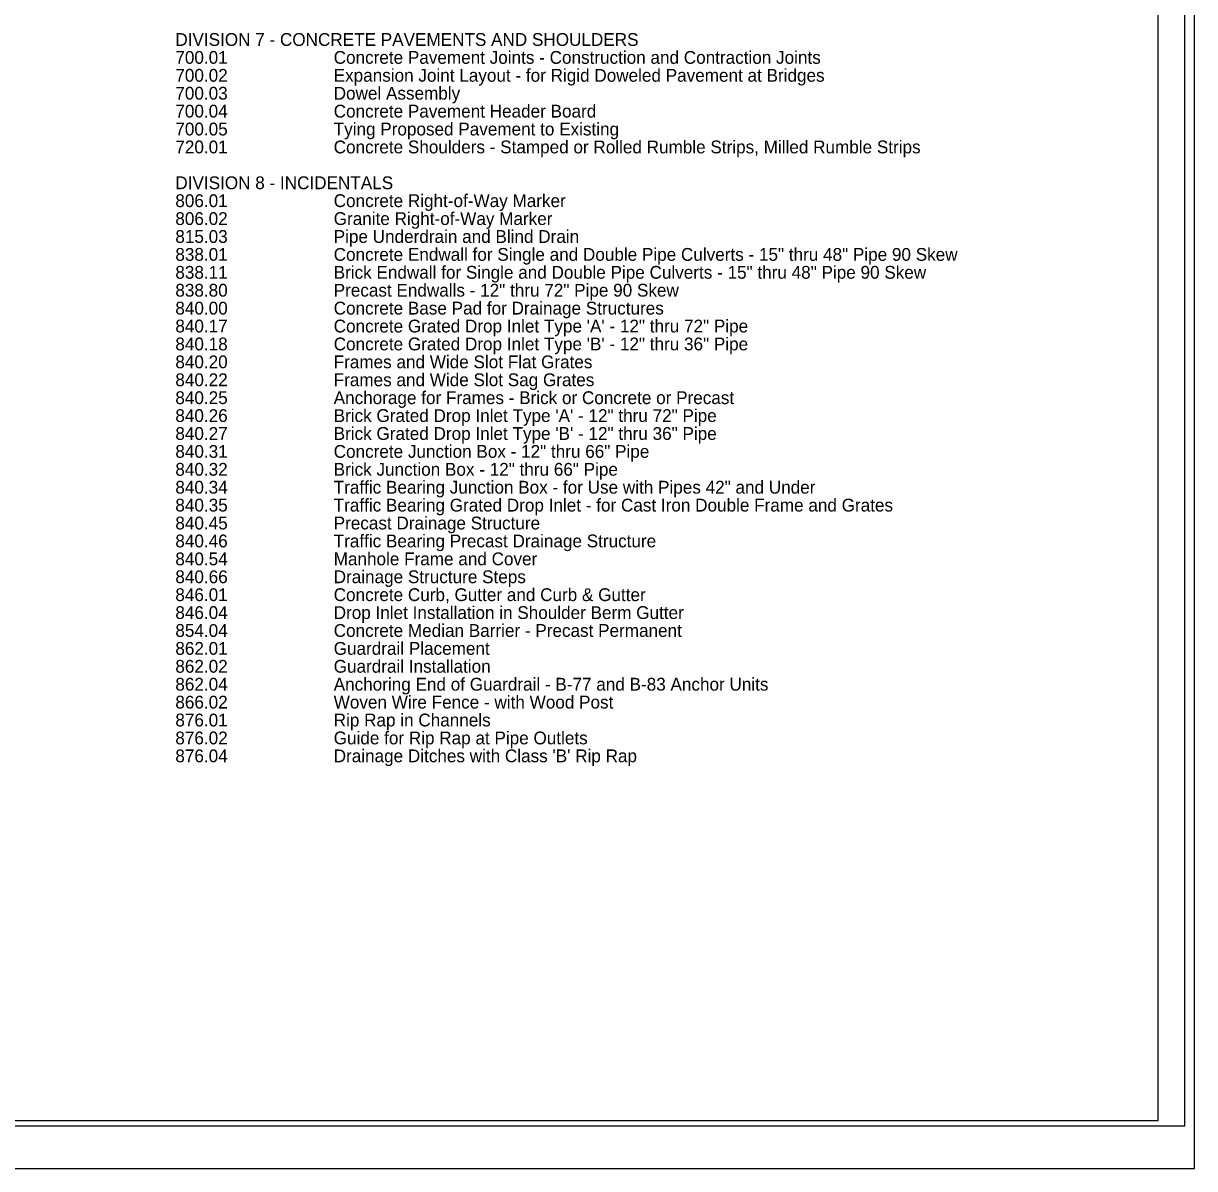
# Model space of a CAD drawing. Extents: x 2241278 to 2254132, y 649924 to 670434.
# Drawn here: x 2250231 to 2252976, y 649924 to 652610 of the extents above; entities that cross this region are included whole.
import ezdxf

# ---------------------------------------------------------------- set-up
doc = ezdxf.new("R2010")
doc.units = 0
for name, color, linetype in [('Sheet Cutting Line CELL', 7, 'Continuous'), ('Sheet Data Text CELL', 7, 'Continuous'), ('Sheet Plan CELL', 7, 'Continuous'), ('Sheet Plot Border Inside CELL', 7, 'Continuous'), ('Sheet Plot Border Outside CELL', 7, 'Continuous')]:
    doc.layers.add(name, color=color, linetype=linetype)

msp = doc.modelspace()

# ---------------------------------------------------------------- linework, layer by layer
at = {"layer": 'Sheet Cutting Line CELL'}
msp.add_line((2244558.8, 649924.2), (2252976.3, 649924.2), dxfattribs=at)
at = {"layer": 'Sheet Plan CELL'}
msp.add_lwpolyline([(2252891.3, 655286.7), (2245391.3, 655286.7), (2245391.3, 650036.7), (2252891.3, 650036.7)], close=True, dxfattribs=at)
at = {"layer": 'Sheet Plot Border Inside CELL'}
msp.add_lwpolyline([(2244623.8, 650024.2), (2252953.8, 650024.2), (2252953.8, 655299.2), (2244623.8, 655299.2)], close=True, dxfattribs=at)
at = {"layer": 'Sheet Plot Border Outside CELL'}
msp.add_lwpolyline([(2244558.8, 649924.2), (2252976.3, 649924.2), (2252976.3, 655399.2), (2244558.8, 655399.2)], close=True, dxfattribs=at)

# ---------------------------------------------------------------- texts
at = {"layer": 'Sheet Data Text CELL'}
for s, p in [('DIVISION 7 - CONCRETE PAVEMENTS AND SHOULDERS', (2250587.3, 652557.1)), ('700.01', (2250587.3, 652515.1)), (' Concrete Pavement Joints - Construction and Contraction Joints ', (2250947.3, 652515.1)), (' Expansion Joint Layout - for Rigid Doweled Pavement at Bridges', (2250947.3, 652473.1)), ('700.02', (2250587.3, 652473.1)), ('700.03', (2250587.3, 652431.1)), (' Dowel Assembly', (2250947.3, 652431.1)), ('700.04', (2250587.3, 652389.1)), (' Concrete Pavement Header Board', (2250947.3, 652389.1)), ('700.05', (2250587.3, 652347.1)), (' Tying Proposed Pavement to Existing', (2250947.3, 652347.1)), ('720.01', (2250587.3, 652305.1)), (' Concrete Shoulders - Stamped or Rolled Rumble Strips, Milled Rumble Strips', (2250947.3, 652305.1)), ('DIVISION 8 - INCIDENTALS', (2250587.3, 652221.1)), ('806.01', (2250587.3, 652179.1)), (' Concrete Right-of-Way Marker', (2250947.3, 652179.1)), ('806.02', (2250587.3, 652137.1)), (' Granite Right-of-Way Marker', (2250947.3, 652137.1)), ('815.03', (2250587.3, 652095.1)), (' Pipe Underdrain and Blind Drain', (2250947.3, 652095.1)), ('838.01', (2250587.3, 652053.1)), (' Concrete Endwall for Single and Double Pipe Culverts - 15" thru 48" Pipe 90 Skew', (2250947.3, 652053.1)), ('838.11', (2250587.3, 652011.1)), (' Brick Endwall for Single and Double Pipe Culverts - 15" thru 48" Pipe 90 Skew', (2250947.3, 652011.1)), ('838.80', (2250587.3, 651969.1)), (' Precast Endwalls - 12" thru 72" Pipe 90 Skew', (2250947.3, 651969.1)), ('840.00', (2250587.3, 651927.1)), (' Concrete Base Pad for Drainage Structures', (2250947.3, 651927.1)), ('840.17', (2250587.3, 651885.1)), (' Concrete Grated Drop Inlet Type \'A\' - 12" thru 72" Pipe', (2250947.3, 651885.1)), ('840.18', (2250587.3, 651843.1)), (' Concrete Grated Drop Inlet Type \'B\' - 12" thru 36" Pipe', (2250947.3, 651843.1)), ('840.20', (2250587.3, 651801.1)), (' Frames and Wide Slot Flat Grates', (2250947.3, 651801.1)), (' Frames and Wide Slot Sag Grates', (2250947.3, 651759.1)), ('840.22', (2250587.3, 651759.1)), ('840.25', (2250587.3, 651717.1)), (' Anchorage for Frames - Brick or Concrete or Precast', (2250947.3, 651717.1)), ('840.26', (2250587.3, 651675.1)), (' Brick Grated Drop Inlet Type \'A\' - 12" thru 72" Pipe', (2250947.3, 651675.1)), ('840.27', (2250587.3, 651633.1)), (' Brick Grated Drop Inlet Type \'B\' - 12" thru 36" Pipe', (2250947.3, 651633.1)), ('840.31', (2250587.3, 651591.1)), (' Concrete Junction Box - 12" thru 66" Pipe', (2250947.3, 651591.1)), ('840.32', (2250587.3, 651549.1)), (' Brick Junction Box - 12" thru 66" Pipe', (2250947.3, 651549.1)), ('840.34', (2250587.3, 651507.1)), (' Traffic Bearing Junction Box - for Use with Pipes 42" and Under', (2250947.3, 651507.1)), ('840.35', (2250587.3, 651465.1)), (' Traffic Bearing Grated Drop Inlet - for Cast Iron Double Frame and Grates', (2250947.3, 651465.1)), ('840.45', (2250587.3, 651423.1)), (' Precast Drainage Structure', (2250947.3, 651423.1)), ('840.46', (2250587.3, 651381.1)), (' Traffic Bearing Precast Drainage Structure', (2250947.3, 651381.1)), ('840.54', (2250587.3, 651339.1)), (' Manhole Frame and Cover', (2250947.3, 651339.1)), ('840.66', (2250587.3, 651297.1)), (' Drainage Structure Steps', (2250947.3, 651297.1)), ('846.01', (2250587.3, 651255.1)), (' Concrete Curb, Gutter and Curb & Gutter', (2250947.3, 651255.1)), ('846.04', (2250587.3, 651213.1)), (' Drop Inlet Installation in Shoulder Berm Gutter', (2250947.3, 651213.1)), ('854.04', (2250587.3, 651171.1)), (' Concrete Median Barrier - Precast Permanent', (2250947.3, 651171.1)), ('862.01', (2250587.3, 651129.1)), (' Guardrail Placement', (2250947.3, 651129.1)), ('862.02', (2250587.3, 651087.1)), (' Guardrail Installation', (2250947.3, 651087.1)), (' Anchoring End of Guardrail - B-77 and B-83 Anchor Units', (2250947.3, 651045.1)), ('862.04', (2250587.3, 651045.1)), ('866.02', (2250587.3, 651003.1)), (' Woven Wire Fence - with Wood Post', (2250947.3, 651003.1)), ('876.01', (2250587.3, 650961.1)), (' Rip Rap in Channels', (2250947.3, 650961.1)), ('876.02', (2250587.3, 650919.1)), (' Guide for Rip Rap at Pipe Outlets', (2250947.3, 650919.1)), ('876.04', (2250587.3, 650877.1)), (" Drainage Ditches with Class 'B' Rip Rap", (2250947.3, 650877.1))]:
    msp.add_text(s, height=30, dxfattribs=at).set_placement(p)

doc.saveas('drawing.dxf')
